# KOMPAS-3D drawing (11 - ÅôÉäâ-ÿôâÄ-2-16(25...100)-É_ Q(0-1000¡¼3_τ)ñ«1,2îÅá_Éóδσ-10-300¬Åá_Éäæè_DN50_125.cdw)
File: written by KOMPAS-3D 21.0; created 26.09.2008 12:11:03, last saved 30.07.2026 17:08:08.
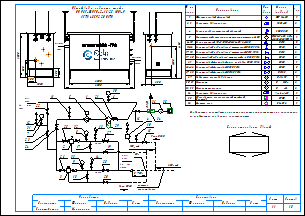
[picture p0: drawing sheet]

Sheets 1-2: A3, landscape

Document properties: Наименование: Макро:21; Автор: RaskoAdmin; Форматы листов документа: 2xA3; Полное имя файла: \\ur38nt01\Departments\КТО\КБ ПУРДГ\Заявки\Прайс-лист на типовые шкафы ГРПШ\ПУРДГ_стандарт_30_04_2026\ПУРДГ с РДСК\ПУРДГ-ШУГО-2-16(25...100)-Р_ Q(0-1000нм3_ч)до1,2МПа_Рвых-10-300кПа_РДСК_DN50_125.cdw

Title block, sheet 1: Наименование: Пункт учета газа / ПУГ-Ш-400-Р / ЛГТИ.485922.001ТУ; designation: ЛГТИ.03.4411141; sheet number: 1; Количество листов документа: 2; organisation: ООО "ЭЛЬСТЕР Газэлектроника"; Форматы листов документа: A3; stored path: C:\Рабочие документы\Компас\ПУГ\Схема.cdw; Разработал: Устинов; Проверил: Кошкин; Утвердил: Кошкин
Title block, sheet 2: sheet number: 2; stored path: D:\Рабочие документы\Заявки\ПУРДГ\ПУРДГ-ШУЭО-2-100-Р 4411220.cdw; designation, second copy: ЛГТИ.03.4411141-

Views: Вид 1, Вид 2
Referenced files: wcvoit.frw
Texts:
  Normal
  Общий вид и габариты шкафа
  ПУРДГ-ШУГО-2-16(25...100)-Р
  DN125
  Выход газа
  DN50
  Вход газа
  logo-rasko-ge.png
  DN 1
  местное
  сопротивление
  Римп DN20
  Выход
  газа
  Р=     кПа
  Вход
  Р=       МПа
  PDI
  № на
  схеме
  Усл.
  обозн.
  Марка
  (модель)
  Кол.
  Фильтр газовый фланцевый
  ФГ 16-50
  Регулятор давления газа
  РДСК-50
  Клапан предохранительный сбросной
  КПС DN20
  Измерительный комплекс с ротационным счетчиком Ду50
  СГ-ЭК-Р-(0,2...2,0)-
  Кран кнопочный VE-РАСКО-НЗ-1,6-G1/2-М20
  DN15
  Кран шаровой "под приварку" штуцерный DN20 PN16
  DN20
  Кран шаровой "под приварку" штуцерный DN15 PN16
  Кран шаровой "под приварку" штуцерный п/п DN20 PN16
  Кран шаровой фланцевый с мех. приводом DN50 PN16
  Кран шаровой фланцевый DN50 PN16
  Кран шаровой фланцевый DN125 PN16
  Индикатор перепада давления
  Манометр
  Манометр-напоромер
  Обогреватель газогорелочный шкафной
  (Эльтон")
  Счетчик газа
  Delta 15
  0...     МПа
  0...     кПа
  Venio-A-15
  ОГШН
  BK-G1,6
  Схема открывания дверей
  Предприятие изготовитель может заменять комплектующие на аналогичные,
  не ухудшающие заявленных характеристик.
  Должность
  Конструктор
  Фамилия
  Подпись
  Дата
  Согласовано
  Максимкин
  Лист
  Листов
  POLYLINE_STYLE_0.18_RGB_0_0_0
  POLYLINE_STYLE_0.50_RGB_0_0_0
  POLYLINE_STYLE_0.34_RGB_0_0_0
  PHANTOM_RGB_0_0_0_SC_1_THICK_0.18
  K5LT_THIN_RGB_0_0_0_THICK_0.18
  K5LT32769_RGB_0_0_0_THICK_0.18
  K5LT12_RGB_0_0_0_SC_1_THICK_0.18
  K5LT_DASHED_RGB_0_0_0_SC_1_THICK_0.18
  ACISOTGL_RGB_0_0_0_SC_0.8_THICK_0.25
  CONTINUOUS_RGB_0_127_31_THICK_0.3
  CONTINUOUS_RGB_0_0_255_THICK_0.35
  CONTINUOUS_RGB_255_0_0_THICK_0.35
  POLYLINE_STYLE_0.25_RGB_0_0_0
  CONTINUOUS_RGB_0_0_0_THICK_0.5
  POLYLINE_STYLE_0.35_RGB_0_0_255
  CONTINUOUS_RGB_0_0_0_THICK_0.4
  CONTINUOUS_RGB_0_0_0_THICK_0.35
  НЕВИДИМАЯ_RGB_0_0_0_SC_0.3_THICK_0.25
  СONTINUOUS_RGB_0_0_0_THICK_0.25
  ОСЕВАЯ2_RGB_248_153_30_SC_0.3_THICK_0.25
  Без оформления
Dimensions and other numbers on the sheet: 1; 1500; 250; 300; 1050; 550; 305; 2500; 4130; 2000; 2800; 5,,,7DN 1; 7; 31; 12; 22; 23; 24; 11; 5; 21; 6; 30; 25; 32; 8; 2; 17; 13; 27; 19; 4; 10; 15; 26; 33; 9; 3; 18; 14; 28; 20; 29; 2, 3; 6-10; 11-16; 17, 18; 19, 20; 22-26; 27, 28; 30, 31; 32, 33; 34; 35; 36; 16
